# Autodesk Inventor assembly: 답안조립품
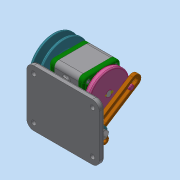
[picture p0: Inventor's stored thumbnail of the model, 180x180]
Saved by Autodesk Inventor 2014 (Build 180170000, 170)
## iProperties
Created: 2020-11
Part Number: 답안조립품
Document SubType Name: Assembly
Designer: net
Mass: 1518.72 g
Surface Area: 1486.39 cm^2
Volume: 467.69 cm^3
Density: 3.24728 g/cm^3
Author: net
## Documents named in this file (19)
- C:\Users\net\Desktop\601106V1045\답안조립품.iam
- C:\Users\net\Desktop\601106V1045\본체.ipt
- C:\Users\net\Desktop\601106V1045\너트 M8.ipt
- C:\Users\net\Desktop\601106V1045\볼트 M4.ipt
- C:\Users\net\Desktop\601106V1045\와셔 8x15.5.ipt
- C:\Users\net\Desktop\601106V1045\크랭크.ipt
- C:\Users\net\Desktop\601106V1045\핀 3 x 8.ipt
- C:\Users\net\Desktop\601106V1045\힌지 축.ipt
- C:\Users\net\Desktop\601106V1045\힌지.ipt
- C:\Users\net\Desktop\601106V1045\V-벨트풀리.ipt
- C:\Users\net\Desktop\601106V1045\돌림판.ipt
- C:\Users\net\Desktop\601106V1045\베어링 6004.ipt
- C:\Users\net\Desktop\601106V1045\오일 실 17 30 5.ipt
- C:\Users\net\Desktop\601106V1045\축.ipt
- C:\Users\net\Desktop\601106V1045\커버.ipt
- C:\Users\net\Desktop\601106V1045\키 5 x 5 x 12.ipt
- C:\Users\net\Desktop\601106V1045\키 4 x 4 x 8.ipt
- C:\Users\net\Desktop\601106V1045\멈춤나사 M3x5.ipt
- C:\Users\net\Desktop\601106V1045\너트 M10x1.ipt
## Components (3 placed, 2 different names)
1. 핀 3 x 8:1
2. 핀 3 x 8:2
3. V-벨트풀리:1
## Named parameters: d24_d21 = 0, d25_d22 = 0
